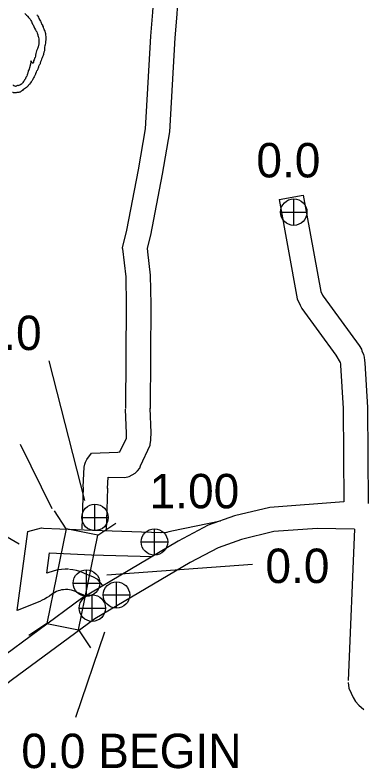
# Model space of a CAD drawing. Extents: x -939622 to -934222, y 1383701 to 1385301.
# Drawn here: x -936019.6 to -936006.77, y 1384124.41 to 1384152.17 of the extents above; entities that cross this region are included whole.
import ezdxf

# ---------------------------------------------------------------- set-up
doc = ezdxf.new("R2010")
doc.units = 0
for name, color, linetype in [('Level 10', 7, 'Continuous'), ('Level 15', 7, 'Continuous'), ('Level 20', 7, 'Continuous'), ('Level 22', 7, 'Continuous'), ('Level 25', 7, 'Continuous'), ('Level 26', 7, 'Continuous'), ('Level 9', 7, 'Continuous')]:
    doc.layers.add(name, color=color, linetype=linetype)

msp = doc.modelspace()

# ---------------------------------------------------------------- linework, layer by layer
at = {"layer": 'Level 10'}
for points in [[(-936014.431, 1384164.496), (-936015.195, 1384158.72), (-936015.205, 1384158.422), (-936015.203, 1384158.293), (-936015.193, 1384158.144), (-936014.542, 1384152.593), (-936014.541, 1384152.455), (-936014.554, 1384152.27), (-936014.627, 1384151.396), (-936014.819, 1384147.974), (-936015.082, 1384146.473), (-936015.507, 1384144.253), (-936015.663, 1384143.597), (-936015.654, 1384143.556), (-936015.535, 1384142.528), (-936015.513, 1384141.502), (-936015.537, 1384137.681)], [(-936013.539, 1384164.378), (-936014.297, 1384158.646), (-936014.305, 1384158.413), (-936014.304, 1384158.331), (-936014.297, 1384158.228), (-936013.643, 1384152.65), (-936013.64, 1384152.427), (-936013.657, 1384152.2), (-936013.729, 1384151.333), (-936013.923, 1384147.87), (-936014.197, 1384146.311), (-936014.626, 1384144.065), (-936014.741, 1384143.584), (-936014.735, 1384143.455), (-936014.736, 1384143.45), (-936014.636, 1384142.59), (-936014.613, 1384141.509), (-936014.637, 1384137.675)], [(-936009.89, 1384145.376), (-936009.004, 1384145.537)], [(-936009.89, 1384145.376), (-936009.223, 1384141.715), (-936009.114, 1384141.483), (-936009.06, 1384141.361), (-936007.804, 1384139.643), (-936007.645, 1384139.373), (-936007.644, 1384139.372), (-936007.636, 1384139.32), (-936007.631, 1384139.278), (-936007.539, 1384137.685), (-936007.512, 1384134.24)], [(-936009.004, 1384145.537), (-936008.359, 1384141.992), (-936008.296, 1384141.858), (-936008.277, 1384141.814), (-936006.946, 1384139.995), (-936006.861, 1384139.861), (-936006.847, 1384139.797), (-936006.792, 1384139.668), (-936006.763, 1384139.564), (-936006.746, 1384139.45), (-936006.734, 1384139.366), (-936006.639, 1384137.714), (-936006.611, 1384134.185)], [(-936015.751, 1384136.079), (-936015.512, 1384136.582), (-936015.508, 1384136.611), (-936015.507, 1384136.62), (-936015.506, 1384136.643), (-936015.501, 1384136.756), (-936015.537, 1384137.66)], [(-936015.109, 1384135.378), (-936015.107, 1384135.381), (-936015.019, 1384135.477), (-936014.994, 1384135.574), (-936014.635, 1384136.331), (-936014.619, 1384136.46), (-936014.617, 1384136.484), (-936014.613, 1384136.521), (-936014.609, 1384136.56), (-936014.598, 1384136.769), (-936014.601, 1384136.785), (-936014.638, 1384137.696)], [(-936017.1, 1384134.789), (-936017.058, 1384135.519), (-936017.039, 1384135.63), (-936017.012, 1384135.702), (-936016.969, 1384135.798), (-936016.798, 1384136.032), (-936015.819, 1384136.076), (-936015.751, 1384136.079)], [(-936016.202, 1384134.737), (-936016.178, 1384135.149), (-936015.571, 1384135.142), (-936015.407, 1384135.17), (-936015.188, 1384135.293), (-936015.135, 1384135.35), (-936015.124, 1384135.362), (-936015.109, 1384135.378)], [(-936017.101, 1384134.778), (-936017.152, 1384133.246)], [(-936016.201, 1384134.748), (-936016.254, 1384133.168)], [(-936007.123, 1384133.238), (-936007.351, 1384127.668)], [(-936007.348, 1384127.593), (-936007.322, 1384127.385), (-936007.243, 1384127.192), (-936007.166, 1384127.042), (-936007.077, 1384126.888), (-936006.958, 1384126.756), (-936006.781, 1384126.598)]]:
    msp.add_lwpolyline(points, dxfattribs=at)
at = {"layer": 'Level 15'}
for points in [[(-936007.512, 1384134.24), (-936010.23, 1384134.038), (-936011.539, 1384133.721), (-936012.5, 1384133.38), (-936013.607, 1384132.795), (-936017.163, 1384130.687)], [(-936014.087, 1384133.115), (-936014.023, 1384133.128), (-936013.941, 1384133.149), (-936013.839, 1384133.169), (-936012.053, 1384133.539)], [(-936019.522, 1384130.238), (-936019.135, 1384133.155), (-936018.632, 1384133.279), (-936018.553, 1384133.267), (-936016.756, 1384133.195), (-936014.225, 1384133.118)], [(-936007.123, 1384133.238), (-936008.497, 1384133.264), (-936010.09, 1384133.146), (-936011.282, 1384132.858), (-936012.137, 1384132.554), (-936013.167, 1384132.009), (-936016.665, 1384129.936)], [(-936014.248, 1384133.118), (-936014.013, 1384133.123)], [(-936018.432, 1384131.616), (-936018.333, 1384132.358), (-936016.788, 1384132.296), (-936014.563, 1384132.228)], [(-936017.634, 1384131.757), (-936017.759, 1384131.762), (-936017.9, 1384131.754), (-936018.035, 1384131.734), (-936018.163, 1384131.704), (-936018.432, 1384131.616)], [(-936016.371, 1384131.157), (-936016.457, 1384131.254), (-936016.565, 1384131.382), (-936016.746, 1384131.483), (-936017.021, 1384131.596), (-936017.103, 1384131.631), (-936017.222, 1384131.675), (-936017.35, 1384131.712), (-936017.482, 1384131.74), (-936017.603, 1384131.755)], [(-936017.664, 1384131.008), (-936017.753, 1384131.011), (-936017.824, 1384131.007), (-936017.893, 1384130.997), (-936017.961, 1384130.981), (-936018.023, 1384130.961), (-936018.085, 1384130.935), (-936018.145, 1384130.905), (-936018.206, 1384130.869), (-936018.269, 1384130.826), (-936018.343, 1384130.773), (-936018.43, 1384130.714), (-936018.521, 1384130.661), (-936018.603, 1384130.619), (-936018.698, 1384130.574), (-936019.522, 1384130.238)], [(-936017.028, 1384130.767), (-936017.05, 1384130.794), (-936017.073, 1384130.806), (-936017.31, 1384130.904), (-936017.381, 1384130.934), (-936017.458, 1384130.963), (-936017.531, 1384130.984), (-936017.604, 1384130.999), (-936017.695, 1384131.01)], [(-936017.163, 1384130.687), (-936020.292, 1384128.377), (-936021.36, 1384127.544), (-936023.552, 1384125.807), (-936023.769, 1384125.636), (-936024.002, 1384125.463), (-936024.244, 1384125.3), (-936024.424, 1384125.179), (-936024.715, 1384125.009), (-936024.929, 1384124.899), (-936025.355, 1384124.698), (-936025.789, 1384124.518), (-936026.362, 1384124.274), (-936027.23, 1384123.933), (-936028.386, 1384123.474), (-936029.74, 1384122.918), (-936030.12, 1384122.777), (-936030.481, 1384122.652), (-936031.087, 1384122.468), (-936031.435, 1384122.369), (-936031.903, 1384122.252), (-936032.777, 1384122.046), (-936033.083, 1384121.968), (-936036.154, 1384121.324)], [(-936016.665, 1384129.936), (-936019.748, 1384127.66), (-936020.803, 1384126.837), (-936022.995, 1384125.1), (-936023.223, 1384124.921), (-936023.481, 1384124.728), (-936023.743, 1384124.552), (-936023.947, 1384124.416), (-936024.281, 1384124.22), (-936024.531, 1384124.092), (-936024.99, 1384123.875), (-936025.44, 1384123.688), (-936026.022, 1384123.441), (-936026.899, 1384123.096), (-936028.049, 1384122.639), (-936029.412, 1384122.08), (-936029.816, 1384121.93), (-936030.202, 1384121.796), (-936030.833, 1384121.605), (-936031.203, 1384121.5), (-936031.69, 1384121.378), (-936032.562, 1384121.172), (-936033.438, 1384120.954), (-936035.713, 1384120.501)]]:
    msp.add_lwpolyline(points, dxfattribs=at)
at = {"layer": 'Level 20'}
for p, q in [((-936017.722, 1384133.253), (-936018.159, 1384133.914)), ((-936016.558, 1384133.016), (-936015.898, 1384133.452)), ((-936018.435, 1384129.761), (-936019.095, 1384129.324)), ((-936017.271, 1384129.523), (-936016.834, 1384128.863))]:
    msp.add_line(p, q, dxfattribs=at)
msp.add_lwpolyline([(-936017.271, 1384129.523), (-936016.558, 1384133.016), (-936017.722, 1384133.253), (-936018.435, 1384129.761)], close=True, dxfattribs=at)
at = {"layer": 'Level 22'}
for points in [[(-936018.363, 1384139.44), (-936017.052, 1384134.296)], [(-936027.679, 1384137.488), (-936019.449, 1384132.696)], [(-936019.421, 1384136.368), (-936018.257, 1384133.995)], [(-936010.87, 1384131.931), (-936016.234, 1384131.542)], [(-936016.316, 1384129.447), (-936017.376, 1384126.294)]]:
    msp.add_lwpolyline(points, dxfattribs=at)
at = {"layer": 'Level 26'}
for p, q in [((-936009.354, 1384144.424), (-936009.354, 1384145.399)), ((-936009.842, 1384144.911), (-936008.867, 1384144.911)), ((-936016.665, 1384133.182), (-936016.665, 1384134.157)), ((-936017.153, 1384133.67), (-936016.178, 1384133.67)), ((-936014.478, 1384132.277), (-936014.478, 1384133.252)), ((-936014.965, 1384132.764), (-936013.99, 1384132.764)), ((-936016.978, 1384130.763), (-936016.978, 1384131.738)), ((-936017.466, 1384131.251), (-936016.491, 1384131.251)), ((-936015.876, 1384130.325), (-936015.876, 1384131.3)), ((-936016.763, 1384129.84), (-936016.763, 1384130.815)), ((-936016.363, 1384130.812), (-936015.388, 1384130.812)), ((-936017.25, 1384130.328), (-936016.275, 1384130.328))]:
    msp.add_line(p, q, dxfattribs=at)
for centre in [(-936009.354, 1384144.911), (-936016.665, 1384133.67), (-936014.478, 1384132.764), (-936016.978, 1384131.251), (-936015.876, 1384130.812), (-936016.763, 1384130.328)]:
    msp.add_circle(centre, 0.487, dxfattribs=at)
at = {"layer": 'Level 9'}
for points in [[(-936019.24, 1384152.229), (-936019.219, 1384152.198), (-936019.181, 1384152.164), (-936019.153, 1384152.135), (-936019.137, 1384152.114), (-936019.114, 1384152.076), (-936019.073, 1384152.036), (-936019.051, 1384152.016), (-936019.035, 1384151.989), (-936019.019, 1384151.972), (-936019.019, 1384151.969), (-936019.003, 1384151.931), (-936018.985, 1384151.892)], [(-936018.809, 1384152.183), (-936018.781, 1384152.154), (-936018.765, 1384152.125), (-936018.748, 1384152.089), (-936018.728, 1384152.045), (-936018.725, 1384152.036), (-936018.689, 1384151.984), (-936018.673, 1384151.945), (-936018.66, 1384151.925), (-936018.646, 1384151.883), (-936018.63, 1384151.857), (-936018.616, 1384151.824), (-936018.6, 1384151.807), (-936018.593, 1384151.774), (-936018.576, 1384151.73), (-936018.566, 1384151.709), (-936018.566, 1384151.706), (-936018.552, 1384151.658), (-936018.529, 1384151.62), (-936018.529, 1384151.611), (-936018.515, 1384151.579), (-936018.503, 1384151.546)], [(-936018.985, 1384151.892), (-936018.958, 1384151.834), (-936018.94, 1384151.804), (-936018.916, 1384151.751), (-936018.885, 1384151.691), (-936018.853, 1384151.63), (-936018.824, 1384151.577), (-936018.804, 1384151.551)], [(-936018.804, 1384151.551), (-936018.788, 1384151.506), (-936018.778, 1384151.477), (-936018.767, 1384151.438), (-936018.767, 1384151.42), (-936018.753, 1384151.381), (-936018.749, 1384151.354), (-936018.727, 1384151.28), (-936018.727, 1384151.262)], [(-936018.503, 1384151.546), (-936018.495, 1384151.521), (-936018.49, 1384151.493), (-936018.486, 1384151.468), (-936018.48, 1384151.427), (-936018.476, 1384151.381), (-936018.473, 1384151.338), (-936018.473, 1384151.309)], [(-936018.727, 1384151.262), (-936018.726, 1384151.244), (-936018.728, 1384151.22), (-936018.728, 1384151.17), (-936018.729, 1384151.112), (-936018.734, 1384151.08), (-936018.741, 1384151.054), (-936018.761, 1384150.994)], [(-936018.473, 1384151.309), (-936018.472, 1384151.282), (-936018.476, 1384151.246), (-936018.479, 1384151.228), (-936018.481, 1384151.204), (-936018.483, 1384151.183)], [(-936018.761, 1384150.994), (-936018.77, 1384150.956), (-936018.775, 1384150.941), (-936018.784, 1384150.922)], [(-936018.517, 1384150.992), (-936018.519, 1384150.979), (-936018.522, 1384150.925), (-936018.523, 1384150.883), (-936018.526, 1384150.864), (-936018.525, 1384150.849), (-936018.536, 1384150.828), (-936018.544, 1384150.797), (-936018.549, 1384150.776), (-936018.554, 1384150.755), (-936018.564, 1384150.715), (-936018.569, 1384150.685)], [(-936018.483, 1384151.183), (-936018.488, 1384151.147), (-936018.5, 1384151.072), (-936018.508, 1384151.039), (-936018.517, 1384150.992)], [(-936018.848, 1384150.696), (-936018.857, 1384150.661), (-936018.869, 1384150.611)], [(-936018.784, 1384150.922), (-936018.803, 1384150.875), (-936018.814, 1384150.847), (-936018.826, 1384150.798), (-936018.838, 1384150.755), (-936018.848, 1384150.696)], [(-936018.569, 1384150.685), (-936018.579, 1384150.658), (-936018.591, 1384150.627), (-936018.608, 1384150.592), (-936018.627, 1384150.548), (-936018.649, 1384150.499), (-936018.666, 1384150.448)], [(-936019.03, 1384150.453), (-936019.027, 1384150.442), (-936019.031, 1384150.408), (-936019.039, 1384150.381), (-936019.039, 1384150.378), (-936019.041, 1384150.366), (-936019.055, 1384150.326), (-936019.054, 1384150.314), (-936019.059, 1384150.277), (-936019.066, 1384150.244), (-936019.072, 1384150.238), (-936019.076, 1384150.207), (-936019.082, 1384150.189), (-936019.092, 1384150.161), (-936019.104, 1384150.146), (-936019.121, 1384150.118), (-936019.125, 1384150.085), (-936019.128, 1384150.079), (-936019.13, 1384150.048), (-936019.135, 1384150.033), (-936019.146, 1384150.005), (-936019.156, 1384149.969), (-936019.178, 1384149.923), (-936019.186, 1384149.907), (-936019.198, 1384149.892), (-936019.2, 1384149.886), (-936019.209, 1384149.87), (-936019.216, 1384149.84), (-936019.227, 1384149.818)], [(-936019.003, 1384150.455), (-936019.009, 1384150.464), (-936019.015, 1384150.469), (-936019.023, 1384150.47), (-936019.028, 1384150.466), (-936019.034, 1384150.458), (-936019.03, 1384150.453)], [(-936018.928, 1384150.458), (-936018.933, 1384150.431), (-936018.947, 1384150.4), (-936018.959, 1384150.399), (-936018.984, 1384150.422), (-936018.987, 1384150.431), (-936018.987, 1384150.434), (-936018.99, 1384150.437), (-936019.003, 1384150.455)], [(-936018.886, 1384150.58), (-936018.895, 1384150.555), (-936018.908, 1384150.522), (-936018.921, 1384150.482), (-936018.928, 1384150.458)], [(-936018.869, 1384150.611), (-936018.886, 1384150.58)], [(-936018.677, 1384150.415), (-936018.68, 1384150.406), (-936018.681, 1384150.376), (-936018.692, 1384150.354), (-936018.715, 1384150.329)], [(-936018.666, 1384150.448), (-936018.672, 1384150.436), (-936018.677, 1384150.415)], [(-936018.743, 1384150.28), (-936018.748, 1384150.249), (-936018.755, 1384150.216), (-936018.766, 1384150.194), (-936018.771, 1384150.173), (-936018.782, 1384150.148), (-936018.794, 1384150.13), (-936018.811, 1384150.111), (-936018.81, 1384150.099), (-936018.816, 1384150.089), (-936018.824, 1384150.065), (-936018.832, 1384150.05), (-936018.835, 1384150.04), (-936018.851, 1384150), (-936018.85, 1384149.991)], [(-936018.715, 1384150.329), (-936018.743, 1384150.28)], [(-936019.227, 1384149.818), (-936019.252, 1384149.781), (-936019.275, 1384149.749), (-936019.293, 1384149.722), (-936019.321, 1384149.681)], [(-936018.85, 1384149.991), (-936018.875, 1384149.939), (-936018.904, 1384149.888), (-936018.925, 1384149.859), (-936018.956, 1384149.804), (-936018.956, 1384149.797)], [(-936019.678, 1384149.598), (-936019.671, 1384149.589), (-936019.661, 1384149.58), (-936019.646, 1384149.57), (-936019.631, 1384149.561), (-936019.607, 1384149.553), (-936019.586, 1384149.553), (-936019.57, 1384149.557), (-936019.535, 1384149.564)], [(-936019.493, 1384149.571), (-936019.511, 1384149.571), (-936019.535, 1384149.564)], [(-936019.493, 1384149.571), (-936019.453, 1384149.587), (-936019.429, 1384149.602), (-936019.393, 1384149.619), (-936019.368, 1384149.63), (-936019.332, 1384149.666)], [(-936019.321, 1384149.681), (-936019.332, 1384149.666)], [(-936019.102, 1384149.597), (-936019.115, 1384149.585), (-936019.123, 1384149.57), (-936019.129, 1384149.566), (-936019.146, 1384149.539), (-936019.157, 1384149.529)], [(-936018.973, 1384149.763), (-936018.99, 1384149.738), (-936019.016, 1384149.707), (-936019.043, 1384149.667), (-936019.073, 1384149.624), (-936019.102, 1384149.597)], [(-936018.956, 1384149.797), (-936018.965, 1384149.785), (-936018.973, 1384149.763)], [(-936019.422, 1384149.331), (-936019.425, 1384149.33), (-936019.44, 1384149.327), (-936019.461, 1384149.323), (-936019.479, 1384149.319), (-936019.497, 1384149.315), (-936019.509, 1384149.315), (-936019.527, 1384149.314), (-936019.539, 1384149.313), (-936019.565, 1384149.306), (-936019.568, 1384149.306), (-936019.571, 1384149.306), (-936019.601, 1384149.302), (-936019.616, 1384149.301), (-936019.625, 1384149.3), (-936019.653, 1384149.305), (-936019.662, 1384149.305), (-936019.68, 1384149.313), (-936019.689, 1384149.319), (-936019.704, 1384149.321)], [(-936019.305, 1384149.422), (-936019.337, 1384149.387), (-936019.37, 1384149.362), (-936019.394, 1384149.348), (-936019.422, 1384149.331)], [(-936019.157, 1384149.529), (-936019.183, 1384149.504), (-936019.222, 1384149.475), (-936019.26, 1384149.45), (-936019.305, 1384149.422)]]:
    msp.add_lwpolyline(points, dxfattribs=at)

# ---------------------------------------------------------------- texts
at = {"layer": 'Level 25'}
for s, p in [('0.0', (-936010.729, 1384146.19)), ('0.0', (-936020.983, 1384139.832)), ('1.00', (-936014.656, 1384134.004)), ('0.0', (-936010.397, 1384131.252)), ('0.0 BEGIN', (-936019.375, 1384124.436))]:
    msp.add_text(s, height=1.2672, dxfattribs=at).set_placement(p)

doc.saveas('drawing.dxf')
